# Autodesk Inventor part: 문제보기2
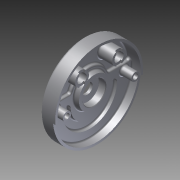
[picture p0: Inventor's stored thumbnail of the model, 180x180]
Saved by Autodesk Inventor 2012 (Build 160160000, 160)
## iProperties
Created: 2015-04
Part Number: 문제보기2
Material: Default
Document SubType Name: Modeling
Designer: Owner
Density: 1 g/cm^3
Author: Owner
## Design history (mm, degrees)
sketch "스케치2"
  geometry: C1 r 95 at (0, 0); 1 further point
  constraints: 1 centre point, 1 coincident
  dimensions: "d3" = 190 diameter of C1
extrude "돌출1" new body sketch "스케치2" distance "d4" = 32; taper "d5" = 0 deg
sketch "스케치3"
  geometry: C1 r 95 at (0, 0) reference; C2 r 90 at (0, 0)
  constraints: 1 centre point, 1 coincident
  dimensions: "d6" = 180 diameter of C2
extrude "돌출2" cut sketch "스케치3" distance "d7" = 20.5; taper "d8" = 0 deg
sketch "스케치4"
  geometry: L1 (-79.667, -14)-(79.667, -14); C1 r 90 at (0, 0) reference; C2 r 90 at (0, 0) reference; C3 r 90 at (0, 0) reference; C4 r 95 at (0, 0) reference; A1 r 41 centre (0, -14) between (-41, -14) and (41, -14); A2 r 59 centre (0, -14) between (-59, -14) and (59, -14); A3 r 9 centre (-50, -14) between (-41, -14) and (-59, -14); A4 r 9 centre (50, -14) between (59, -14) and (41, -14); 1 further point
  constraints: 8 point on circle, 4 centre point, 2 coincident, 2 end point, 2 point on line, 2 tangent, 1 horizontal, 1 midpoint, 1 vertical alignment
  dimensions: "d9" = 14 distance from line of C1.centre L1; "d10" = 82 diameter of A1; "d11" = 118 diameter of A2; "d12" = 18 diameter of A3; "d13" = 18 diameter of A4
extrude "돌출3" cut sketch "스케치4" distance "d14" = 7; taper "d15" = 0 deg
sketch "스케치5"
  geometry: L1 (-83.283, 12)-(83.283, 12); C1 r 90 at (0, 0) reference; A1 r 42 centre (0, 0) between (40.249, 12) and (-40.249, 12); A2 r 5 centre (-83.283, 17) between (-88.182, 18) and (-83.283, 12); A3 r 5 centre (83.283, 17) between (83.283, 12) and (88.182, 18); A4 r 90 centre (0, 0) between (-88.182, 18) and (88.182, 18) reference; A5 r 5 centre (-43.818, 17) between (-43.818, 12) and (-39.156, 15.191); A6 r 5 centre (43.818, 17) between (39.156, 15.191) and (43.818, 12); A7 r 90 centre (0, 0) between (88.182, 18) and (-88.182, 18)
  constraints: 16 point on circle, 8 tangent, 6 centre point, 4 point on line, 2 coincident, 2 end point, 1 horizontal
  dimensions: "d16" = 84 diameter of A1; "d17" = 12 distance from line of L1 A1.centre; "d18" = 10 diameter of A2; "d19" = 10 diameter of A3; "d20" = 10 diameter of A5; "d21" = 10 diameter of A6
extrude "돌출4" cut sketch "스케치5" distance "d22" = 7; taper "d23" = 0 deg
sketch "스케치6"
  geometry: L1 (-83.283, 12)-(-43.818, 12) reference; L2 (-56.202, 52)-(58.852, 52); L3 (0, 0)-(0, 134.318); C1 r 15 at (-40, 52); A1 r 42 centre (0, 0) between (39.156, 15.191) and (-39.156, 15.191) reference; A2 r 90 centre (0, 0) between (88.182, 18) and (-88.182, 18) reference
  constraints: 4 end point, 1 centre point, 1 parallel, 1 perpendicular, 1 point on line
  dimensions: "d24" = 52 distance from line of L2 A1.centre; "d25" = 30 diameter of C1; "d26" = 40 distance from line of L3 C1.centre
extrude "돌출5" join sketch "스케치6" distance "d27" = 30.5; taper "d28" = 0 deg
sketch "스케치7"
  geometry: C1 r 15 at (0, 0) reference; C2 r 10 at (0, 0); 1 further point
  constraints: 1 centre point, 1 coincident
  dimensions: "d29" = 20 diameter of C2
extrude "돌출6" cut sketch "스케치7" stored distance "d30" = 30.5; taper "d31" = 0 deg
sketch "스케치8"
  geometry: L1 (6, 13.748)-(6, 8); L2 (6, -8)-(6, -13.748); L3 (0, 15)-(0, 10); L4 (0, -10)-(0, -15); L5 (-6, 13.748)-(-6, 8); L6 (-6, -8)-(-6, -13.748); C1 r 10 at (0, 0) reference; C2 r 15 at (0, 0) reference; A1 r 10 centre (0, 0) between (6, 8) and (6, -8); A2 r 15 centre (0, 0) between (-6, 13.748) and (0, 15); 4 further points
  constraints: 12 end point, 12 point on circle, 8 parallel, 3 coincident, 2 centre point, 2 concentric, 2 midpoint, 2 vertical, 2 vertical alignment
  dimensions: "d34" = 6 distance between parallel lines of L5 L3; "d35" = 6 distance between parallel lines of L3 L1; "d36" = 6 distance between parallel lines of L4 L2; "d37" = 6 distance between parallel lines of L6 L4
extrude "돌출7" cut sketch "스케치8" distance "d38" = 3; taper "d39" = 0 deg
sketch "스케치9"
  geometry: C1 r 35 at (0, 0); A1 r 90 centre (0, 0) between (-88.182, 18) and (88.182, 18) reference
  constraints: 1 centre point, 1 coincident
  dimensions: "d40" = 70 diameter of C1
extrude "돌출8" join sketch "스케치9" distance "d41" = 10; taper "d42" = -10 deg
hole "구멍1" diameter "d45" = 23; stored, may be unused: countersink angle "d49" = 90 deg, drill point angle "d51" = 118 deg; dims "d43" = 10, "d44" = 10, "d46" = 6, "d47" = 50, "d48" = 15, "d50" = 8
sketch "스케치10"
  geometry: L1 (-43.818, 12)-(-83.283, 12) reference; L2 (-83.283, 0)-(79.95, 0); C1 r 9 at (-74, 0); C2 r 9 at (74, 0); A1 r 90 centre (0, 0) between (-88.182, 18) and (88.182, 18) reference; A2 r 15 centre (-40, 52) between (-46, 65.748) and (-46, 38.252) reference; A3 r 74 centre (0, 0) between (-74, 0) and (74, 0)
  constraints: 3 centre point, 2 end point, 2 point on circle, 2 point on line, 1 coincident, 1 parallel
  dimensions: "d52" = 52 distance from line of A2.centre L2; "d53" = 148 diameter of A3; "d54" = 18 diameter of C1; "d55" = 18 diameter of C2
extrude "돌출9" join sketch "스케치10" distance "d56" = 25; taper "d57" = 0 deg
hole "구멍2" diameter "d60" = 11; stored, may be unused: countersink angle "d64" = 90 deg, drill point angle "d66" = 0 deg; dims "d58" = 10, "d59" = 10, "d61" = 6, "d62" = 18, "d63" = 15, "d65" = 11
sketch "스케치11"
  geometry: C1 r 5.5 at (74, 0) reference; C2 r 9 at (74, 0)
  constraints: 1 centre point, 1 coincident
  dimensions: "d67" = 18 diameter of C2
extrude "돌출10" cut sketch "스케치11" distance "d68" = 11; taper "d69" = 0 deg
sketch "스케치12"
  geometry: C1 r 9 at (0, 0) reference; C2 r 5.5 at (0, 0); 1 further point
  constraints: 1 centre point, 1 coincident
  dimensions: "d70" = 11 diameter of C2
extrude "돌출11" cut sketch "스케치12" stored distance "d71" = 11; taper "d72" = 0 deg
sketch "스케치13"
  geometry: C1 r 5.5 at (-74, 0) reference; C2 r 9 at (-74, 0)
  constraints: 1 centre point, 1 coincident
  dimensions: "d73" = 18 diameter of C2
extrude "돌출12" cut sketch "스케치13" distance "d74" = 11; taper "d75" = 0 deg
sketch "스케치14"
  geometry: L1 (0, 0)-(0, -72); L2 (0, 0)-(-8.132, -8.132); L3 (-36.062, -36.062)-(-50.912, -50.912); L4 (0, 0)-(8.132, -8.132); L5 (36.062, -36.062)-(50.912, -50.912); C1 r 95 at (0, 0) reference; A1 r 11.5 centre (0, 0) between (-8.132, -8.132) and (8.132, -8.132) reference; A2 r 72 centre (0, 0) between (0, -72) and (-50.912, -50.912); A3 r 51 centre (0, 0) between (-36.062, -36.062) and (36.062, -36.062)
  constraints: 10 end point, 7 point on circle, 2 centre point, 2 coincident, 1 vertical
  dimensions: "d76" = 144 diameter of A2; "d77" = 102 diameter of A3; "d80" = 45 deg angle of L1 L5; "d81" = 45 deg angle of L1 L3
extrude "돌출13" join sketch "스케치14" distance "d82" = 5; taper "d83" = 0 deg
sketch "스케치15"
  geometry: C1 r 88 at (0, 0); A1 r 72 centre (0, 0) between (-50.912, -50.912) and (50.912, -50.912) reference; A2 r 51 centre (0, 0) between (-36.062, -36.062) and (36.062, -36.062) reference
  constraints: 1 centre point, 1 coincident, 1 other
  dimensions: "d84" = 176 diameter of C1
extrude "돌출14" join sketch "스케치15" distance "d85" = 0.5; taper "d86" = 0 deg
fillet "모깎기1" dims "d87" = 5
fillet "모깎기2" dims "d88" = 4
chamfer "모따기1" distance "d89" = 1; stored, may be unused: second distance "d90" = 2, angle "d91" = 45 deg
chamfer "모따기2" distance "d92" = 1; stored, may be unused: second distance "d93" = 2, angle "d94" = 45 deg
fillet "모깎기3" dims "d95" = 5
sketch "스케치16"
  geometry: L1 (-95, 0)-(95, 0); L2 (0, 0)-(-94.638, -8.28); L3 (0, 0)-(94.638, -8.28); C1 r 90 at (0, 0) reference; A1 r 95 centre (0, 0) between (-94.638, -8.28) and (94.638, -8.28) reference; A2 r 95 centre (0, 0) between (95, 0) and (-95, 0); A3 r 95 centre (0, 0) between (-94.638, -8.28) and (94.638, -8.28); A4 r 90 centre (0, 0) between (90, 0) and (-90, 0); A5 r 90 centre (0, 0) between (-89.658, -7.844) and (89.658, -7.844)
  constraints: 10 point on circle, 6 end point, 4 centre point, 4 point on line, 3 coincident, 1 horizontal
  dimensions: "d96" = 5 deg angle of L1 L2; "d97" = 5 deg angle of L1 L3
extrude "돌출15" cut sketch "스케치16" distance "d98" = 5; taper "d99" = 0 deg; dims "d54" = 18
fillet "모깎기4" dims "d100" = 3
fillet "모깎기5" dims "d101" = 0.3
fillet "모깎기6" dims "d102" = 3
fillet "모깎기7" dims "d103" = 3
fillet "모깎기8" dims "d104" = 3
fillet "모깎기9" dims "d105" = 3
node "솔리드2"
mirror "대칭1"
node "투영된 루프1"
other parameters: "d32" = 6, "d33" = 6, "d78" = 45 deg, "d79" = 45 deg
